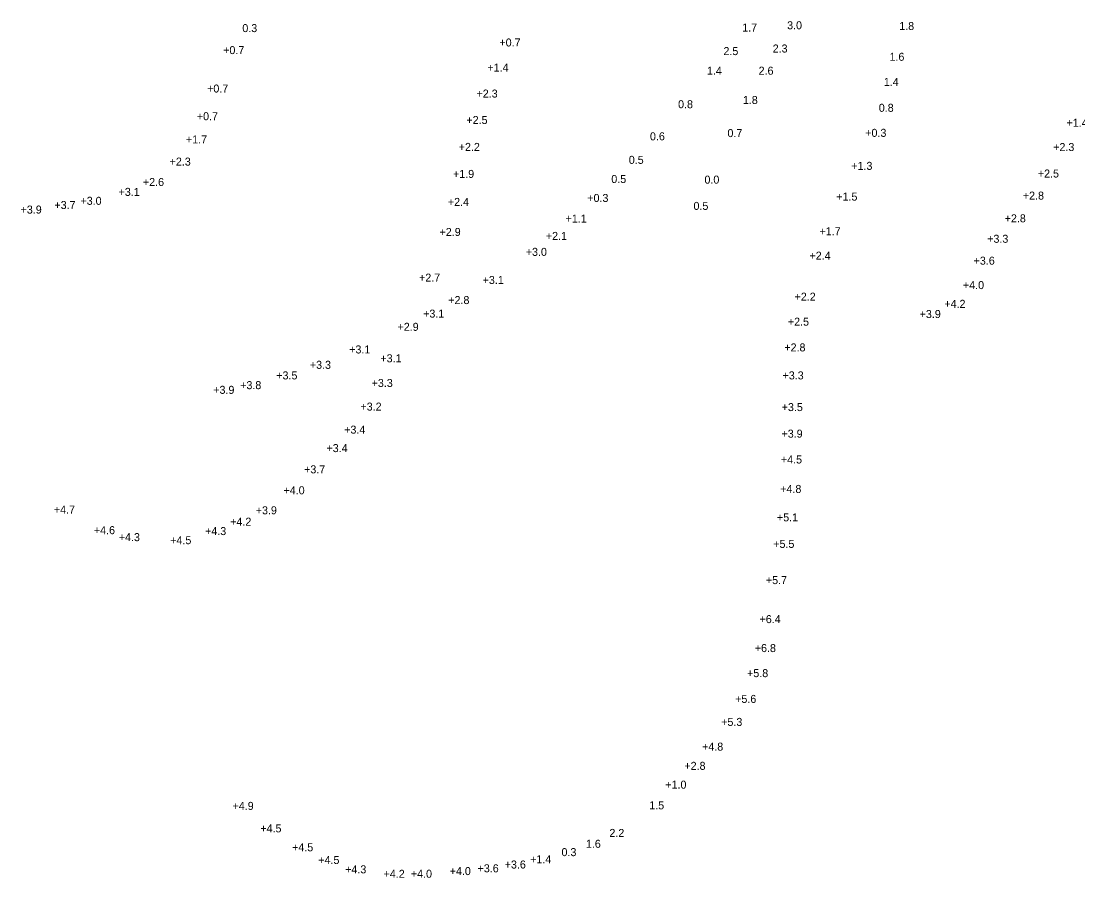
# Model space of a CAD drawing. Extents: x 837127 to 848654, y 3074248 to 3079868.
# Drawn here: x 845678.8 to 846091.6, y 3077895.1 to 3078229.7 of the extents above; entities that cross this region are included whole.
import ezdxf

# ---------------------------------------------------------------- set-up
doc = ezdxf.new("R2010")
doc.units = 0
doc.layers.add('V-HYDS-SOUN', color=7, linetype='Continuous')
doc.layers.add('V-HYDS-SOUN-EXSS', color=7, linetype='Continuous')

msp = doc.modelspace()

# ---------------------------------------------------------------- texts
at = {"layer": 'V-HYDS-SOUN'}
for s, p in [('0.3', (845765.23, 3078225.37)), ('1.7', (845960.47, 3078225.58)), ('3.0', (845978.01, 3078226.48)), ('1.8', (846021.8, 3078226.19)), ('+0.7 ', (845757.75, 3078216.78)), ('+0.7 ', (845865.64, 3078219.75)), ('2.5', (845953.14, 3078216.39)), ('2.3', (845972.37, 3078217.4)), ('1.6', (846018, 3078214.17)), ('+1.4 ', (845860.96, 3078209.96)), ('1.4', (845946.7, 3078208.74)), ('2.6', (845966.87, 3078208.73)), ('1.4', (846015.78, 3078204.37)), ('+0.7 ', (845751.48, 3078201.77)), ('+2.3 ', (845856.7, 3078199.8)), ('0.8', (845935.42, 3078195.64)), ('1.8', (845960.73, 3078197.28)), ('0.8', (846013.81, 3078194.25)), ('+0.7 ', (845747.47, 3078190.96)), ('+2.5 ', (845852.75, 3078189.49)), ('+1.4 ', (846087.12, 3078188.41)), ('0.7', (845954.7, 3078184.37)), ('+0.3 ', (846008.52, 3078184.47)), ('+1.7 ', (845743.2, 3078181.87)), ('0.6', (845924.44, 3078183.11)), ('+2.2 ', (845849.75, 3078178.97)), ('+2.3 ', (846081.93, 3078178.91)), ('+2.3 ', (845736.84, 3078173.24)), ('0.5', (845916.17, 3078173.92)), ('+1.3 ', (846003.07, 3078171.57)), ('+1.9 ', (845847.52, 3078168.43)), ('+2.5 ', (846075.94, 3078168.58)), ('+2.6 ', (845726.41, 3078165.26)), ('0.5', (845909.34, 3078166.44)), (' 0.0', (845944.56, 3078166.19)), ('+3.1 ', (845716.9, 3078161.41)), ('+0.3 ', (845899.96, 3078159.04)), ('+1.5 ', (845997.21, 3078159.56)), ('+2.8 ', (846070.08, 3078159.96)), ('+3.9 ', (845678.63, 3078154.5)), ('+3.7 ', (845691.84, 3078156.29)), ('+3.0 ', (845702.01, 3078157.93)), ('+2.4 ', (845845.52, 3078157.49)), ('0.5', (845941.44, 3078155.94)), ('+1.1 ', (845891.48, 3078151)), ('+2.8 ', (846062.98, 3078151.08)), ('+2.9 ', (845842.26, 3078145.76)), ('+2.1 ', (845883.79, 3078144.21)), ('+1.7 ', (845990.64, 3078146.05)), ('+3.3 ', (846056.15, 3078143.1)), ('+3.0 ', (845875.94, 3078137.99)), ('+2.4 ', (845986.74, 3078136.51)), ('+2.7 ', (845834.26, 3078127.93)), ('+3.1 ', (845859.09, 3078127.01)), ('+4.0 ', (846046.68, 3078125.01)), ('+2.8 ', (845845.67, 3078119.16)), ('+2.2 ', (845980.92, 3078120.49)), ('+4.2 ', (846039.43, 3078117.69)), ('+3.1 ', (845835.85, 3078113.87)), ('+3.9 ', (846029.77, 3078113.71)), ('+2.5 ', (845978.3, 3078110.72)), ('+2.9 ', (845825.85, 3078108.71)), ('+2.8 ', (845976.92, 3078100.67)), ('+3.1 ', (845806.97, 3078099.88)), ('+3.3 ', (845791.6, 3078093.88)), ('+3.1 ', (845819.15, 3078096.43)), ('+3.5 ', (845778.49, 3078089.74)), ('+3.3 ', (845976.22, 3078089.74)), ('+3.8 ', (845764.39, 3078085.93)), ('+3.3 ', (845815.74, 3078086.79)), ('+3.9 ', (845753.88, 3078084.1)), ('+3.2 ', (845811.36, 3078077.56)), ('+3.5 ', (845975.89, 3078077.37)), ('+3.4 ', (845805.01, 3078068.57)), ('+3.9 ', (845975.81, 3078067)), ('+3.4 ', (845798.09, 3078061.35)), ('+4.5 ', (845975.59, 3078056.91)), ('+3.7 ', (845789.36, 3078053.06)), ('+4.0 ', (845781.32, 3078044.87)), ('+4.8 ', (845975.32, 3078045.41)), ('+4.7 ', (845691.64, 3078037.33)), ('+3.9 ', (845770.48, 3078037.07)), ('+4.2 ', (845760.49, 3078032.61)), ('+5.1 ', (845974.04, 3078034.31)), ('+4.6 ', (845707.26, 3078029.3)), ('+4.3 ', (845716.99, 3078026.58)), ('+4.3 ', (845750.69, 3078028.95)), ('+4.5 ', (845737.07, 3078025.39)), ('+5.5 ', (845972.6, 3078023.94)), ('+5.7 ', (845969.72, 3078009.8)), ('+6.4 ', (845967.24, 3077994.57)), ('+6.8 ', (845965.38, 3077983.26)), ('+5.8 ', (845962.37, 3077973.47)), ('+5.6 ', (845957.71, 3077963.4)), ('+5.3 ', (845952.26, 3077954.42)), ('+4.8 ', (845944.8, 3077944.77)), ('+2.8 ', (845937.89, 3077937.27)), ('+1.0 ', (845930.43, 3077929.92)), ('+4.9 ', (845761.41, 3077921.63)), ('1.5', (845924.16, 3077921.85)), ('+4.5 ', (845772.26, 3077912.84)), ('2.2', (845908.6, 3077911.07)), ('1.6', (845899.42, 3077906.82)), ('+4.5 ', (845784.67, 3077905.46)), ('0.3', (845889.89, 3077903.57)), ('+4.5 ', (845794.9, 3077900.51)), ('+3.6 ', (845867.71, 3077898.73)), ('+1.4 ', (845877.63, 3077900.8)), ('+4.3 ', (845805.4, 3077896.85)), ('+4.2 ', (845820.4, 3077895.1)), ('+4.0 ', (845831.06, 3077895.13)), ('+4.0 ', (845846.23, 3077896.18)), ('+3.6 ', (845857.11, 3077897.25))]:
    msp.add_text(s, height=3.125, dxfattribs=at).set_placement(p)
at = {"layer": 'V-HYDS-SOUN-EXSS'}
msp.add_text('+3.6 ', height=3.125, dxfattribs=at).set_placement((846050.85, 3078134.55))

doc.saveas('drawing.dxf')
